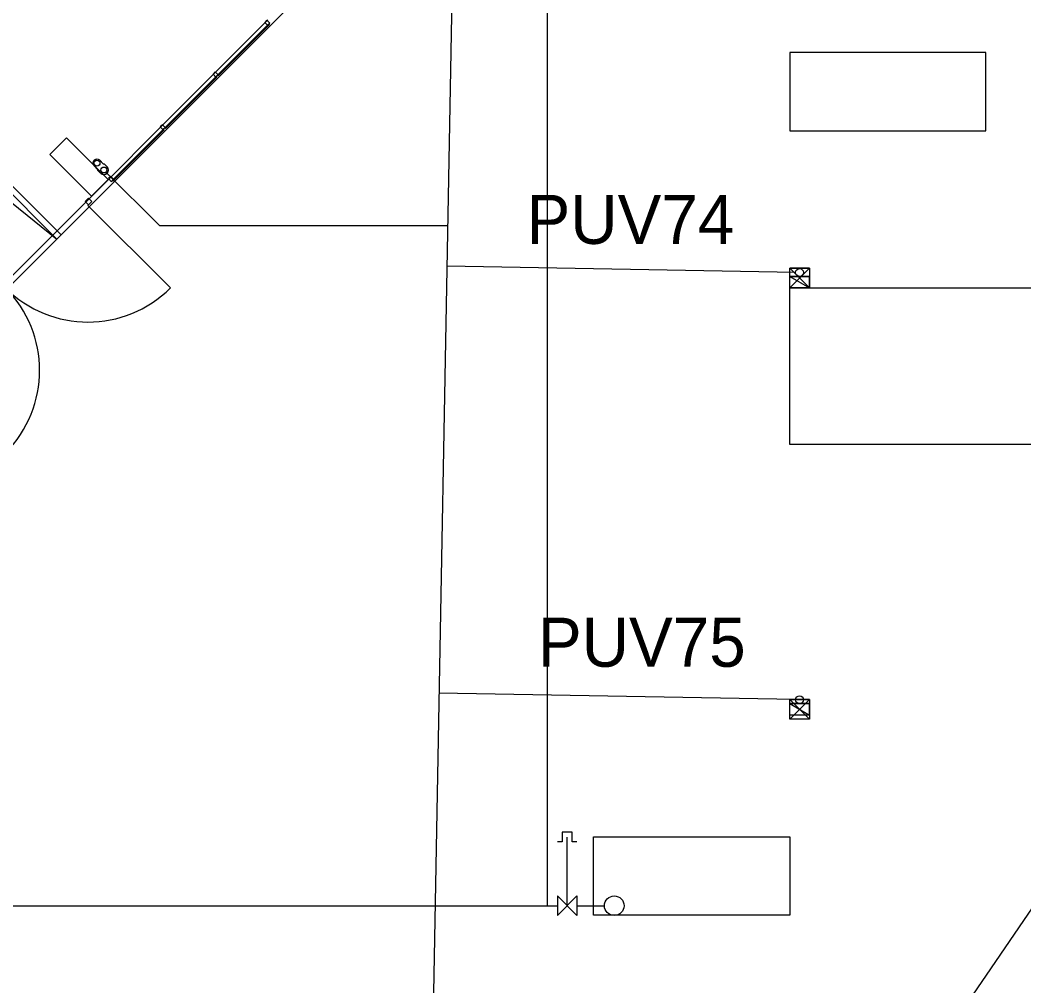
# Model space of a CAD drawing. Extents: x -264234 to -263604, y -1242346 to -1242049.
# Drawn here: x -263801.59 to -263776, y -1242252.19 to -1242227.55 of the extents above; entities that cross this region are included whole.
import ezdxf

# ---------------------------------------------------------------- set-up
doc = ezdxf.new("R2010")
doc.units = 0
for name, color, linetype in [('KFA_JESTV_IS_DSP_-_KANAL_DAZD', 7, 'Continuous'), ('KFA_SITUACIA_DSP', 7, 'Continuous'), ('KFA_SO_40-2-II_DK_PRIPOJKY_UV_PROJEKT', 7, 'Continuous'), ('KFA_SO_40-2-II_DK_PRIPOJKY_UV_PROJEKT_popis', 7, 'Continuous'), ('KFA_SO_40-2-II_DK_UV_PROJEKT', 7, 'Continuous')]:
    doc.layers.add(name, color=color, linetype=linetype)

msp = doc.modelspace()

# ---------------------------------------------------------------- linework, layer by layer
at = {"layer": 'KFA_JESTV_IS_DSP_-_KANAL_DAZD'}
msp.add_line((-263790.323, -1242212.531), (-263791.054, -1242252.363), dxfattribs=at)
at = {"layer": 'KFA_SITUACIA_DSP'}
for p, q in [((-263788.143, -1242250.14), (-263788.143, -1242082.64)), ((-263798.899, -1242284.125), (-263751.864, -1242215.081)), ((-263795.272, -1242227.55), (-263808.8, -1242241.078)), ((-263796.558, -1242228.963), (-263795.25, -1242227.654)), ((-263795.232, -1242227.672), (-263796.541, -1242228.98)), ((-263795.297, -1242227.56), (-263795.354, -1242227.617)), ((-263795.354, -1242227.617), (-263795.283, -1242227.688)), ((-263795.227, -1242227.631), (-263795.297, -1242227.56)), ((-263795.283, -1242227.688), (-263795.255, -1242227.659)), ((-263795.255, -1242227.659), (-263795.227, -1242227.631)), ((-263795.25, -1242227.654), (-263795.232, -1242227.672)), ((-263805.389, -1242228.403), (-263800.652, -1242233.141)), ((-263805.283, -1242228.297), (-263800.546, -1242233.035)), ((-263781.968, -1242228.382), (-263781.968, -1242230.382)), ((-263776.968, -1242228.382), (-263781.968, -1242228.382)), ((-263776.968, -1242230.382), (-263776.968, -1242228.382)), ((-263796.59, -1242228.994), (-263797.898, -1242230.303)), ((-263797.881, -1242230.32), (-263796.572, -1242229.012)), ((-263796.617, -1242228.879), (-263796.673, -1242228.936)), ((-263796.673, -1242228.936), (-263796.602, -1242229.007)), ((-263796.546, -1242228.95), (-263796.617, -1242228.879)), ((-263796.602, -1242229.007), (-263796.574, -1242228.978)), ((-263796.572, -1242229.012), (-263796.59, -1242228.994)), ((-263796.574, -1242228.978), (-263796.546, -1242228.95)), ((-263796.541, -1242228.98), (-263796.558, -1242228.963)), ((-263797.961, -1242230.223), (-263798.017, -1242230.28)), ((-263798.017, -1242230.28), (-263797.946, -1242230.351)), ((-263797.89, -1242230.294), (-263797.961, -1242230.223)), ((-263797.918, -1242230.322), (-263797.89, -1242230.294)), ((-263797.898, -1242230.303), (-263797.881, -1242230.32)), ((-263800.834, -1242230.985), (-263800.41, -1242230.561)), ((-263800.41, -1242230.561), (-263799.349, -1242231.622)), ((-263797.934, -1242230.338), (-263799.242, -1242231.647)), ((-263799.225, -1242231.664), (-263797.916, -1242230.356)), ((-263797.946, -1242230.351), (-263797.918, -1242230.322)), ((-263797.916, -1242230.356), (-263797.934, -1242230.338)), ((-263781.968, -1242230.382), (-263776.968, -1242230.382)), ((-263799.774, -1242232.046), (-263800.834, -1242230.985)), ((-263799.705, -1242231.275), (-263799.617, -1242231.364)), ((-263799.559, -1242231.13), (-263799.471, -1242231.218)), ((-263799.471, -1242231.218), (-263799.451, -1242231.218)), ((-263799.373, -1242231.296), (-263799.451, -1242231.218)), ((-263799.451, -1242231.218), (-263799.373, -1242231.296)), ((-263799.617, -1242231.364), (-263799.617, -1242231.383)), ((-263799.617, -1242231.383), (-263799.538, -1242231.462)), ((-263799.402, -1242231.432), (-263798.041, -1242232.793)), ((-263799.28, -1242231.543), (-263799.336, -1242231.599)), ((-263799.209, -1242231.613), (-263799.28, -1242231.543)), ((-263799.349, -1242231.622), (-263799.774, -1242232.046)), ((-263799.336, -1242231.599), (-263799.266, -1242231.67)), ((-263799.266, -1242231.67), (-263799.237, -1242231.642)), ((-263799.242, -1242231.647), (-263799.225, -1242231.664)), ((-263799.237, -1242231.642), (-263799.209, -1242231.613)), ((-263799.929, -1242232.178), (-263799.844, -1242232.093)), ((-263799.844, -1242232.093), (-263799.759, -1242232.178)), ((-263799.844, -1242232.263), (-263799.929, -1242232.178)), ((-263799.844, -1242232.263), (-263799.862, -1242232.281)), ((-263799.862, -1242232.281), (-263797.758, -1242234.384)), ((-263799.759, -1242232.178), (-263799.844, -1242232.263)), ((-263798.041, -1242232.793), (-263790.695, -1242232.793)), ((-263781.818, -1242233.99), (-263790.714, -1242233.827)), ((-263781.968, -1242234.092), (-263781.468, -1242234.092)), ((-263781.968, -1242234.382), (-263781.968, -1242234.092)), ((-263781.968, -1242234.092), (-263781.468, -1242234.382)), ((-263781.968, -1242234.092), (-263781.468, -1242234.382)), ((-263781.468, -1242234.092), (-263781.968, -1242234.092)), ((-263781.468, -1242234.092), (-263781.468, -1242234.382)), ((-263781.468, -1242234.382), (-263781.468, -1242234.092)), ((-263781.468, -1242234.382), (-263781.968, -1242234.382)), ((-263781.968, -1242234.382), (-263771.968, -1242234.382)), ((-263781.968, -1242238.382), (-263781.968, -1242234.382)), ((-263781.968, -1242234.382), (-263781.968, -1242234.382)), ((-263771.968, -1242238.382), (-263781.968, -1242238.382)), ((-263781.818, -1242244.885), (-263790.914, -1242244.718)), ((-263781.968, -1242244.987), (-263781.468, -1242244.987)), ((-263781.968, -1242245.277), (-263781.968, -1242244.987)), ((-263781.968, -1242244.987), (-263781.468, -1242245.277)), ((-263781.968, -1242244.987), (-263781.468, -1242245.277)), ((-263781.468, -1242244.987), (-263781.968, -1242244.987)), ((-263781.468, -1242244.987), (-263781.468, -1242245.277)), ((-263781.468, -1242245.277), (-263781.468, -1242244.987)), ((-263781.468, -1242245.277), (-263781.968, -1242245.277)), ((-263787.768, -1242248.265), (-263787.768, -1242248.515)), ((-263787.518, -1242248.265), (-263787.768, -1242248.265)), ((-263787.643, -1242250.14), (-263787.643, -1242248.39)), ((-263787.518, -1242248.515), (-263787.518, -1242248.265)), ((-263787.768, -1242248.515), (-263787.893, -1242248.515)), ((-263787.393, -1242248.515), (-263787.518, -1242248.515)), ((-263787.893, -1242250.39), (-263787.393, -1242249.89)), ((-263787.893, -1242249.89), (-263787.893, -1242250.39)), ((-263787.393, -1242250.39), (-263787.893, -1242249.89)), ((-263787.393, -1242249.89), (-263787.393, -1242250.39)), ((-263924.143, -1242250.14), (-263788.143, -1242250.14)), ((-263788.143, -1242250.14), (-263787.893, -1242250.14)), ((-263788.143, -1242250.14), (-263787.893, -1242250.14)), ((-263787.393, -1242250.14), (-263786.693, -1242250.14))]:
    msp.add_line(p, q, dxfattribs=at)
for points in [[(-263794.893, -1242227.382), (-263808.968, -1242241.457), (-263894.968, -1242241.457), (-263909.043, -1242227.382), (-263909.043, -1242196.333), (-263914.143, -1242196.333), (-263914.143, -1242132.433), (-263909.043, -1242132.433), (-263909.043, -1242101.382), (-263894.968, -1242087.307), (-263808.968, -1242087.307), (-263794.893, -1242101.382), (-263794.893, -1242227.382)], [(-263803.204, -1242235.693), (-263813.559, -1242222.704), (-263800.652, -1242233.141)]]:
    msp.add_lwpolyline(points, dxfattribs=at)
msp.add_lwpolyline([(-263786.968, -1242248.382), (-263781.968, -1242248.382), (-263781.968, -1242250.382), (-263786.968, -1242250.382)], close=True, dxfattribs=at)
for centre, radius in [((-263799.632, -1242231.202), 0.075), ((-263799.455, -1242231.379), 0.075), ((-263781.718, -1242233.992), 0.1), ((-263781.718, -1242244.887), 0.1), ((-263786.443, -1242250.14), 0.25)]:
    msp.add_circle(centre, radius, dxfattribs=at)
for centre, radius, start, end in [((-263799.632, -1242231.202), 0.103, 45, 225), ((-263799.455, -1242231.379), 0.117, 225, 45), ((-263804.069, -1242236.488), 2.975, 315.0001, 45.0001), ((-263799.862, -1242232.281), 2.975, 224.9999, 314.9999)]:
    msp.add_arc(centre, radius, start, end, dxfattribs=at)
at = {"layer": 'KFA_SO_40-2-II_DK_PRIPOJKY_UV_PROJEKT'}
for points in [[(-263781.818, -1242233.99), (-263790.714, -1242233.827)], [(-263781.818, -1242244.885), (-263790.914, -1242244.718)]]:
    msp.add_lwpolyline(points, dxfattribs=at)
at = {"layer": 'KFA_SO_40-2-II_DK_UV_PROJEKT'}
for points in [[(-263781.968, -1242234.382), (-263781.968, -1242233.882), (-263781.468, -1242233.882), (-263781.468, -1242234.382), (-263781.968, -1242234.382), (-263781.468, -1242233.882), (-263781.968, -1242233.882), (-263781.468, -1242234.382)], [(-263781.968, -1242245.382), (-263781.968, -1242244.882), (-263781.468, -1242244.882), (-263781.468, -1242245.382), (-263781.968, -1242245.382), (-263781.468, -1242244.882), (-263781.968, -1242244.882), (-263781.468, -1242245.382)]]:
    msp.add_lwpolyline(points, dxfattribs=at)

# ---------------------------------------------------------------- texts
at = {"layer": 'KFA_SO_40-2-II_DK_PRIPOJKY_UV_PROJEKT_popis'}
for s, p in [('PUV74', (-263788.679, -1242233.263)), ('PUV75', (-263788.388, -1242244.047))]:
    msp.add_text(s, height=1.25, dxfattribs=at).set_placement(p)

doc.saveas('drawing.dxf')
